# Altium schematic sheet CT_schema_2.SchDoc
size 379 x 215 mm
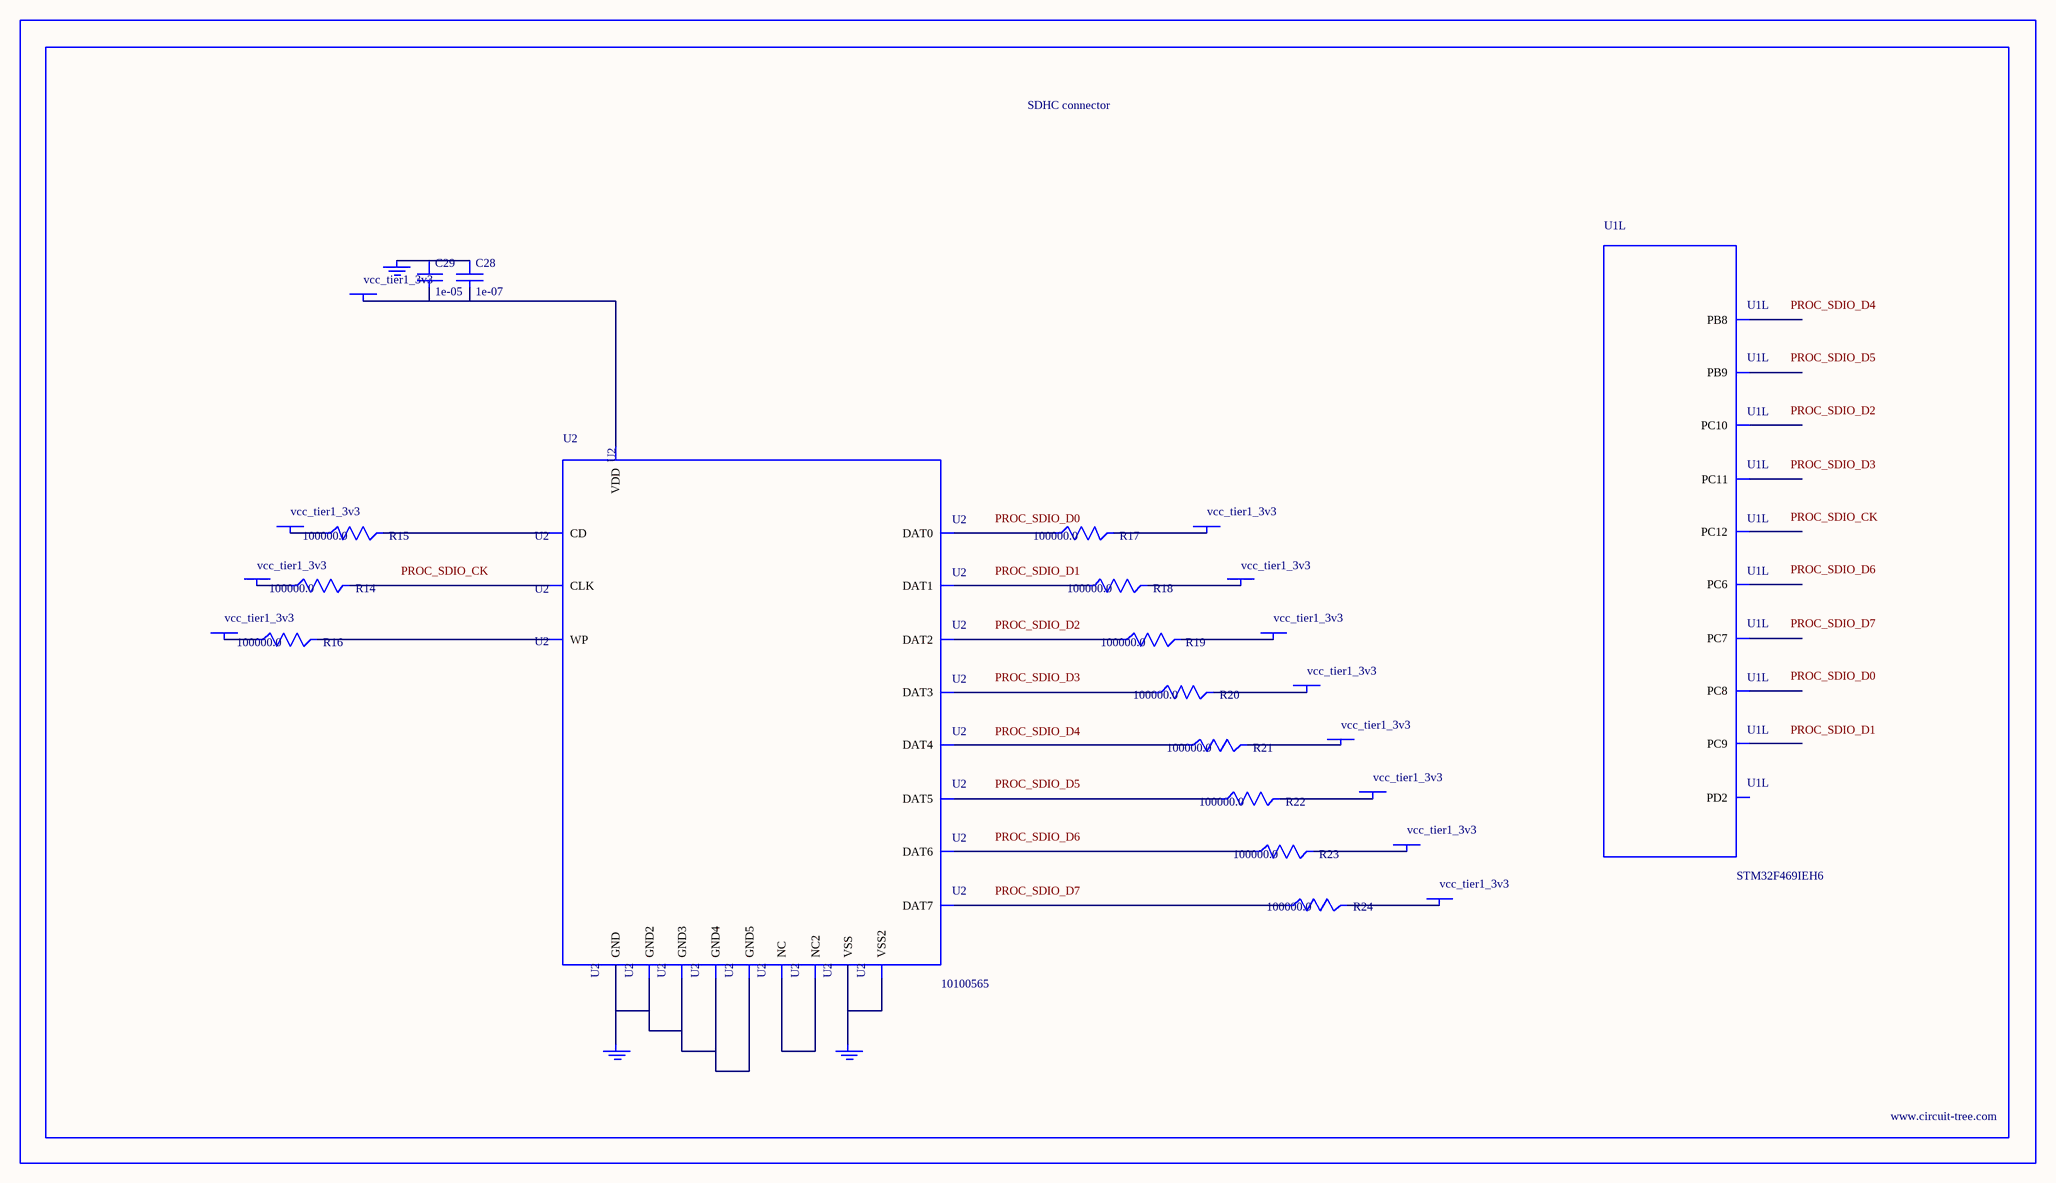
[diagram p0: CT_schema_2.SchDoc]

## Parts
BORDER1  (no value)
C28  1e-07  [C0402]
C29  1e-05  [C0805]
GND_INSTANCE_1_0  (no value)
GND_INSTANCE_1_1  (no value)
GND_INSTANCE_1_2  (no value)
POWER_INSTANCE_1_0  vcc_tier1_3v3
POWER_INSTANCE_1_1  vcc_tier1_3v3
POWER_INSTANCE_1_2  vcc_tier1_3v3
POWER_INSTANCE_1_3  vcc_tier1_3v3
POWER_INSTANCE_1_4  vcc_tier1_3v3
POWER_INSTANCE_1_5  vcc_tier1_3v3
POWER_INSTANCE_1_6  vcc_tier1_3v3
POWER_INSTANCE_1_7  vcc_tier1_3v3
POWER_INSTANCE_1_8  vcc_tier1_3v3
POWER_INSTANCE_1_9  vcc_tier1_3v3
POWER_INSTANCE_1_10  vcc_tier1_3v3
POWER_INSTANCE_1_11  vcc_tier1_3v3
R14  100000.0  [R0603]
R15  100000.0  [R0603]
R16  100000.0  [R0603]
R17  100000.0  [R0603]
R18  100000.0  [R0603]
R19  100000.0  [R0603]
R20  100000.0  [R0603]
R21  100000.0  [R0603]
R22  100000.0  [R0603]
R23  100000.0  [R0603]
R24  100000.0  [R0603]
U1  STM32F469IEH6  [UFBGA176]  (part L of 16)
U2  10100565  [10100565]

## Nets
NetC28_1: C28.1 C29.1 GND_INSTANCE_1_0.0(GND)
NetC28_2: C28.2 C29.2 POWER_INSTANCE_1_7.0(PWR) U2.9(VDD)
NetGND_INSTANCE_1_1_0: GND_INSTANCE_1_1.0(GND) U2.6(VSS) U2.10(VSS2)
NetGND_INSTANCE_1_2_0: GND_INSTANCE_1_2.0(GND) U2.12(GND) U2.16(GND2) U2.17(GND3) U2.20(GND4) U2.21(GND5)
NetPOWER_INSTANCE_1_0_0: POWER_INSTANCE_1_0.0(PWR) R16.1
NetPOWER_INSTANCE_1_1_0: POWER_INSTANCE_1_1.0(PWR) R15.1
NetPOWER_INSTANCE_1_2_0: POWER_INSTANCE_1_2.0(PWR) R18.2
NetPOWER_INSTANCE_1_3_0: POWER_INSTANCE_1_3.0(PWR) R17.2
NetPOWER_INSTANCE_1_4_0: POWER_INSTANCE_1_4.0(PWR) R24.2
NetPOWER_INSTANCE_1_5_0: POWER_INSTANCE_1_5.0(PWR) R23.2
NetPOWER_INSTANCE_1_6_0: POWER_INSTANCE_1_6.0(PWR) R14.1
NetPOWER_INSTANCE_1_8_0: POWER_INSTANCE_1_8.0(PWR) R22.2
NetPOWER_INSTANCE_1_9_0: POWER_INSTANCE_1_9.0(PWR) R21.2
NetPOWER_INSTANCE_1_10_0: POWER_INSTANCE_1_10.0(PWR) R20.2
NetPOWER_INSTANCE_1_11_0: POWER_INSTANCE_1_11.0(PWR) R19.2
NetR14_2: R14.2 U2.8(CLK)
NetR15_2: R15.2 U2.2(CD)
NetR16_2: R16.2 U2.1(WP)
NetR17_1: R17.1 U2.4(DAT0)
NetR18_1: R18.1 U2.3(DAT1)
NetR19_1: R19.1 U2.15(DAT2)
NetR20_1: R20.1 U2.14(DAT3)
NetR21_1: R21.1 U2.13(DAT4)
NetR22_1: R22.1 U2.11(DAT5)
NetR23_1: R23.1 U2.7(DAT6)
NetR24_1: R24.1 U2.5(DAT7)
NetU2_18: U2.18(NC) U2.19(NC2)

Not connected (* = marked no-connect by the designer): U1 A5(PB8) A12(PC12) B4(PB9) B13(PC11) B14(PC10) D12(PD2) F14(PC9) G14(PC8) G15(PC7) H15(PC6)

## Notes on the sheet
- Labels drawn without touching a wire or pin: PROC_SDIO_CK, PROC_SDIO_D0, PROC_SDIO_D1, PROC_SDIO_D2, PROC_SDIO_D3, PROC_SDIO_D4, PROC_SDIO_D5, PROC_SDIO_D6, PROC_SDIO_D7

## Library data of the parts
BORDER1 = BORDER_PAGE1
C28 = C0402C104K3RACTU
C29 = C0805C106K8RACTU
GND_INSTANCE_1_0-GND_INSTANCE_1_2 = GND
POWER_INSTANCE_1_0-POWER_INSTANCE_1_11 = PWR
R14-R24 = RC0603JR-07100KL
